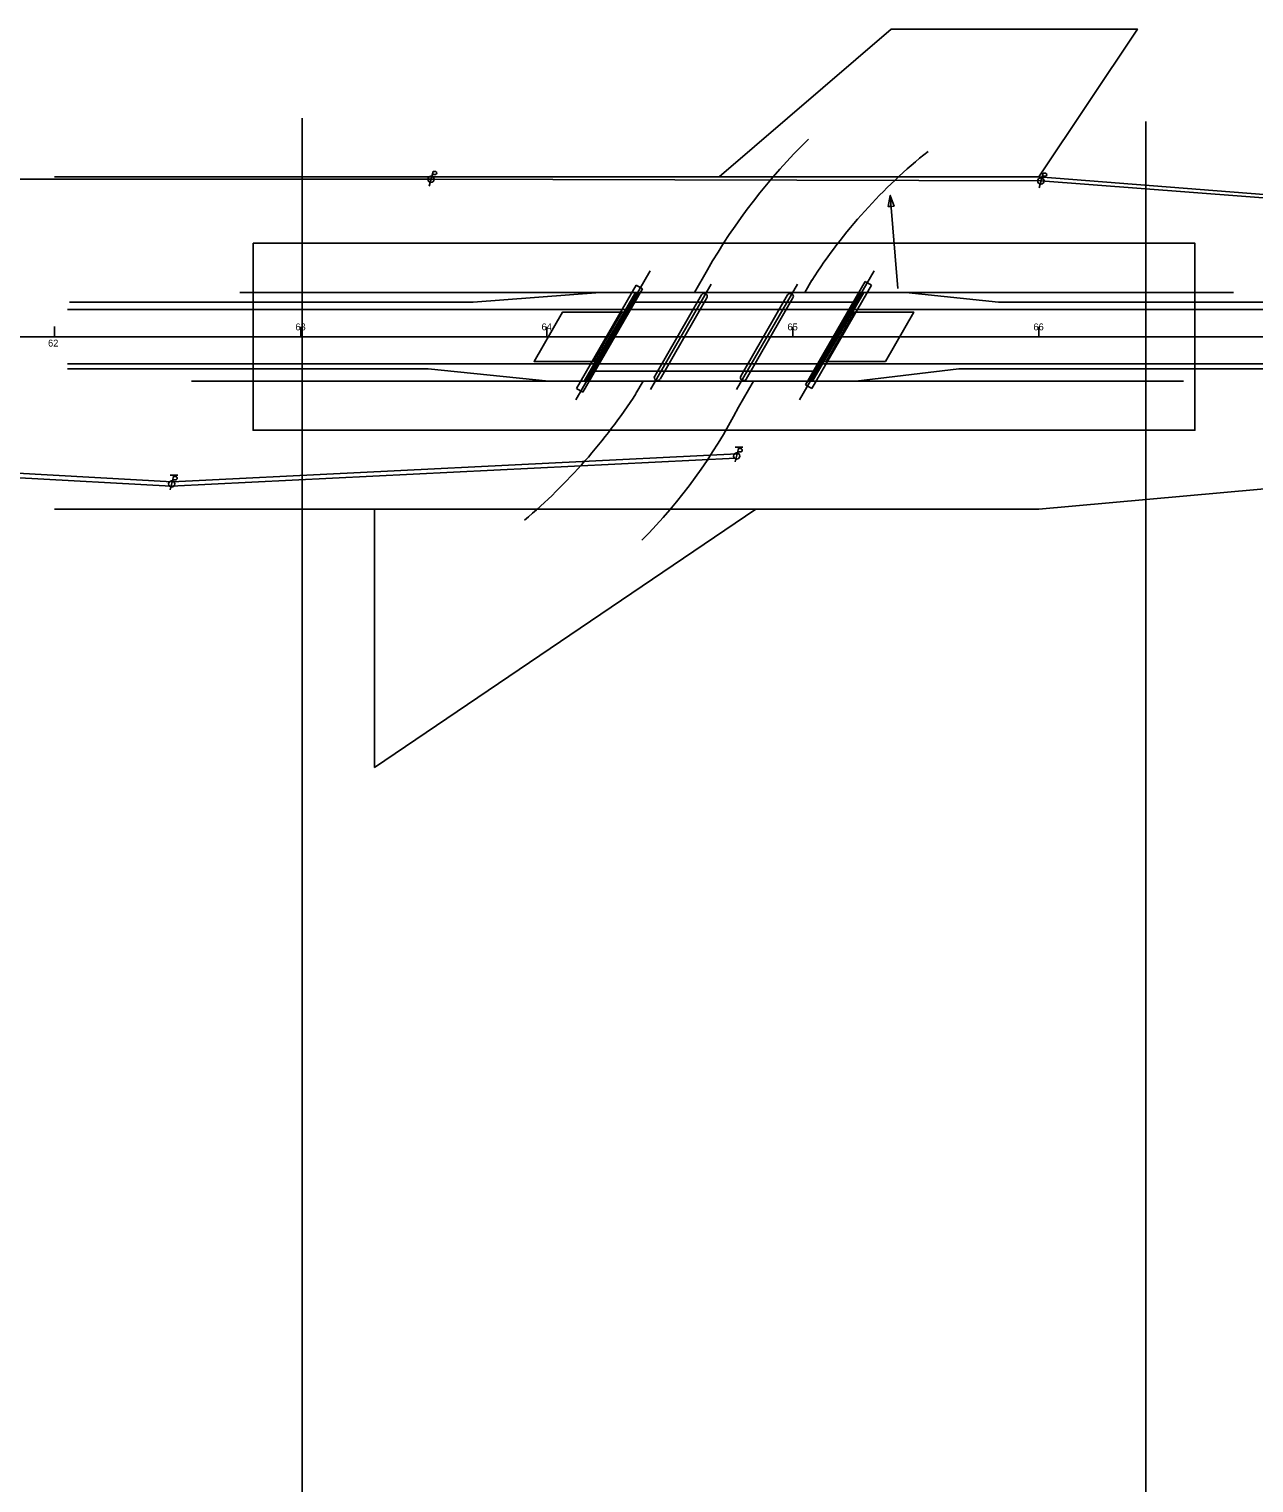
# Model space of a CAD drawing. Extents: x -2222 to 2066, y -217 to 964.
# Drawn here: x -1930 to -1432, y 374 to 964 of the extents above; entities that cross this region are included whole.
import ezdxf

# ---------------------------------------------------------------- set-up
doc = ezdxf.new("R2010")
doc.units = 0
for name, color, linetype in [('BR_X_Brg_Centerline', 7, 'Continuous'), ('BR_X_Slab_Const_Joint', 7, 'Continuous'), ('BR_X_Slab_Object', 7, 'Continuous'), ('BR_X_Sub_Centerline', 7, 'Continuous'), ('BR_X_Sub_Object', 7, 'Continuous'), ('GE_X_CL_20', 7, 'Continuous'), ('HY_X_Water_Edge', 7, 'Continuous'), ('MD_P_CONST_LIMITS', 7, 'Continuous'), ('PM_P_CL_Pass_Proh_Rt', 7, 'Continuous'), ('PM_X_Edge_Line', 7, 'Continuous'), ('PV_P_Shoulder_Rumble_Strip', 7, 'Continuous'), ('PV_X_EOP', 7, 'Continuous'), ('RD_X_GR_Lt', 7, 'Continuous'), ('RD_X_GR_Rt', 7, 'Continuous'), ('RW_X_Esmt_CH', 7, 'Continuous'), ('RW_X_Fee_RW', 7, 'Continuous'), ('SC_Scratch1', 7, 'Continuous'), ('SC_Scratch3', 7, 'Continuous'), ('UT_X_Electric_Cells', 7, 'Continuous'), ('UT_X_Gas', 7, 'Continuous'), ('UT_X_Overhead_Electric', 7, 'Continuous'), ('UT_X_Overhead_Telecom', 7, 'Continuous')]:
    doc.layers.add(name, color=color, linetype=linetype)

msp = doc.modelspace()

# ---------------------------------------------------------------- linework, layer by layer
at = {"layer": 'BR_X_Brg_Centerline'}
for p, q in [((-1677.87, 866.17), (-1708.11, 813.79)), ((-1586.87, 866.17), (-1617.11, 813.79))]:
    msp.add_line(p, q, dxfattribs=at)
at = {"layer": 'BR_X_Slab_Const_Joint'}
for p, q in [((-1686.13, 853.37), (-1593.54, 853.37)), ((-1702.29, 825.37), (-1609.7, 825.37))]:
    msp.add_line(p, q, dxfattribs=at)
at = {"layer": 'BR_X_Slab_Object'}
msp.add_lwpolyline([(-1683.82, 857.37), (-1704.6, 821.37), (-1611.86, 821.37), (-1591.08, 857.37)], close=True, dxfattribs=at)
at = {"layer": 'BR_X_Sub_Centerline'}
for p, q in [((-1677.71, 817.95), (-1653.01, 860.73)), ((-1618, 860.74), (-1642.74, 817.89))]:
    msp.add_line(p, q, dxfattribs=at)
at = {"layer": 'BR_X_Sub_Object'}
for p, q in [((-1683.53, 860.37), (-1707.78, 818.37)), ((-1705.18, 816.87), (-1680.97, 858.8)), ((-1683.09, 857.37), (-1703.88, 821.37)), ((-1703.16, 821.37), (-1682.37, 857.37)), ((-1680.97, 858.8), (-1683.57, 860.3)), ((-1590.5, 861.87), (-1614.74, 819.88)), ((-1613.3, 821.37), (-1592.52, 857.37)), ((-1591.8, 857.37), (-1612.58, 821.37)), ((-1612.15, 818.37), (-1587.9, 860.37)), ((-1587.9, 860.37), (-1590.5, 861.87)), ((-1656.97, 856.37), (-1676.01, 823.4)), ((-1673.84, 822.15), (-1654.81, 855.12)), ((-1621.97, 856.38), (-1641, 823.41)), ((-1638.84, 822.16), (-1619.8, 855.13)), ((-1700.85, 829.37), (-1689.3, 849.37)), ((-1606.38, 829.37), (-1594.83, 849.37)), ((-1707.78, 818.37), (-1705.18, 816.87)), ((-1614.74, 819.88), (-1612.15, 818.38))]:
    msp.add_line(p, q, dxfattribs=at)
for points in [[(-1688.44, 849.37), (-1713.44, 849.37), (-1724.98, 829.37), (-1699.98, 829.37)], [(-1607.24, 829.37), (-1582.24, 829.37), (-1570.7, 849.37), (-1595.7, 849.37)]]:
    msp.add_lwpolyline(points, dxfattribs=at)
for centre, start, end in [((-1655.89, 855.74), 330, 150), ((-1620.88, 855.75), 330, 150), ((-1674.92, 822.77), 150, 324.13716), ((-1639.92, 822.78), 150, 330)]:
    msp.add_arc(centre, 1.25, start, end, dxfattribs=at)
at = {"layer": 'GE_X_CL_20'}
for p, q in [((-1914.68, 839.37), (-1418.65, 839.37)), ((-1819.84, 839.37), (-1819.84, 841.37)), ((-1719.84, 839.37), (-1719.84, 841.37)), ((-1619.84, 839.37), (-1619.84, 841.37)), ((-1519.84, 839.37), (-1519.84, 841.37))]:
    msp.add_line(p, q, dxfattribs=at)
at = {"layer": 'HY_X_Water_Edge'}
for p, q in [((-1659.86, 857.37), (-1654.57, 866.53)), ((-1615.04, 857.37), (-1612.2, 862.29)), ((-1680.64, 821.37), (-1683.61, 816.24)), ((-1635.83, 821.37), (-1641.99, 810.69))]:
    msp.add_line(p, q, dxfattribs=at)
for centre, radius, start, end in [((-1444.17, 746.19), 242.38, 134.30725, 150.23356), ((-1427.35, 742.97), 220.01, 128.70044, 147.15858), ((-1882.04, 945.3), 236.71, 310.32329, 326.95848), ((-1836.67, 910.83), 218.92, 315.25171, 332.77778)]:
    msp.add_arc(centre, radius, start, end, dxfattribs=at)
at = {"layer": 'MD_P_CONST_LIMITS'}
msp.add_lwpolyline([(-1839.21, 877.37), (-1456.47, 877.37), (-1456.47, 801.37), (-1839.21, 801.37)], close=True, dxfattribs=at)
at = {"layer": 'PM_P_CL_Pass_Proh_Rt'}
msp.add_line((-1914.68, 839.37), (-1418.65, 839.37), dxfattribs=at)
at = {"layer": 'PM_X_Edge_Line'}
for p, q in [((-1914.68, 850.37), (-1418.44, 850.37)), ((-1914.68, 828.37), (-1418.44, 828.37))]:
    msp.add_line(p, q, dxfattribs=at)
at = {"layer": 'PV_P_Shoulder_Rumble_Strip'}
for p, q in [((-1694.21, 839.37), (-1744.21, 839.37)), ((-1601.47, 839.37), (-1551.47, 839.37))]:
    msp.add_line(p, q, dxfattribs=at)
at = {"layer": 'PV_X_EOP'}
for points in [[(-1683.82, 857.37), (-1698.13, 857.37), (-1749.77, 853.37), (-1913.75, 853.37)], [(-1591.08, 857.37), (-1573.9, 857.37), (-1536.29, 853.37), (-1361.15, 853.37)], [(-1704.6, 821.37), (-1719.06, 821.37), (-1767.99, 826.37), (-1914.68, 826.37)], [(-1611.86, 821.37), (-1594.23, 821.37), (-1552.45, 826.37), (-1401.79, 826.37)]]:
    msp.add_lwpolyline(points, dxfattribs=at)
at = {"layer": 'RD_X_GR_Lt'}
msp.add_line((-1844.52, 857.37), (-1440.75, 857.37), dxfattribs=at)
at = {"layer": 'RD_X_GR_Rt'}
msp.add_line((-1864.19, 821.37), (-1461.11, 821.37), dxfattribs=at)
at = {"layer": 'RW_X_Esmt_CH'}
for points in [[(-1649.84, 904.37), (-1579.84, 964.37), (-1479.84, 964.37), (-1519.84, 904.37)], [(-1789.84, 769.37), (-1789.84, 664.37), (-1634.84, 769.37)]]:
    msp.add_lwpolyline(points, dxfattribs=at)
at = {"layer": 'RW_X_Fee_RW'}
for points in [[(-1919.84, 904.37), (-1519.84, 904.37), (-1074.8, 869.37)], [(-1919.84, 769.37), (-1519.84, 769.37), (-1074.8, 809.37)]]:
    msp.add_lwpolyline(points, dxfattribs=at)
at = {"layer": 'SC_Scratch1'}
for p, q in [((-1766.75, 903.95), (-1766.58, 904.6)), ((-1518.9, 903.26), (-1518.72, 903.91)), ((-1767.25, 902.09), (-1767.07, 902.74)), ((-1519.4, 901.4), (-1519.22, 902.05)), ((-1914.68, 839.37), (-2219.84, 839.37)), ((-1919.84, 839.37), (-1919.84, 843.57)), ((-1819.84, 841.37), (-1819.84, 843.37)), ((-1719.84, 841.37), (-1719.84, 843.37)), ((-1619.84, 841.37), (-1619.84, 843.37)), ((-1519.84, 841.37), (-1519.84, 843.37)), ((-1642.55, 791.5), (-1642.37, 792.15)), ((-1643.05, 789.64), (-1642.87, 790.29)), ((-1872.14, 780.15), (-1871.97, 780.81)), ((-1872.64, 778.29), (-1872.47, 778.95))]:
    msp.add_line(p, q, dxfattribs=at)
msp.add_lwpolyline([(-1580.28, 896.82), (-1581.12, 892.23), (-1579.91, 892.33), (-1578.7, 892.43), (-1580.27, 896.79), (-1577.2, 858.99)], dxfattribs=at)
at = {"layer": 'SC_Scratch3'}
for p, q in [((-1819.21, 18.08), (-1819.21, 928.19)), ((-1476.47, 16.67), (-1476.47, 926.77))]:
    msp.add_line(p, q, dxfattribs=at)
at = {"layer": 'UT_X_Electric_Cells'}
for p, q in [((-1766.06, 906.54), (-1767.66, 900.54)), ((-1766.4, 905.27), (-1765.21, 905.27)), ((-1766.06, 906.54), (-1765.21, 906.54)), ((-1518.2, 905.85), (-1519.81, 899.85)), ((-1518.55, 904.58), (-1517.35, 904.58)), ((-1518.2, 905.85), (-1517.35, 905.85))]:
    msp.add_line(p, q, dxfattribs=at)
for centre in [(-1766.91, 903.34), (-1519.06, 902.65)]:
    msp.add_circle(centre, 1.3, dxfattribs=at)
for centre in [(-1765.19, 905.91), (-1517.34, 905.21)]:
    msp.add_arc(centre, 0.638, 268.8767, 91.1233, dxfattribs=at)
at = {"layer": 'UT_X_Gas'}
for p, q in [((-1640.15, 794.5), (-1643.35, 794.5)), ((-1641.75, 794.5), (-1643.35, 788.5)), ((-1642.25, 792.62), (-1641.06, 792.62)), ((-1641.91, 793.9), (-1641.06, 793.9)), ((-1871.34, 783.15), (-1872.95, 777.15)), ((-1869.74, 783.15), (-1872.94, 783.15)), ((-1871.84, 781.28), (-1870.65, 781.28)), ((-1871.5, 782.55), (-1870.65, 782.55))]:
    msp.add_line(p, q, dxfattribs=at)
for centre in [(-1642.71, 790.9), (-1872.3, 779.55)]:
    msp.add_circle(centre, 1.3, dxfattribs=at)
for centre in [(-1641.04, 793.26), (-1870.64, 781.91)]:
    msp.add_arc(centre, 0.638, 268.8767, 91.1233, dxfattribs=at)
at = {"layer": 'UT_X_Overhead_Electric'}
for points in [[(-1969.05, 903.34), (-1766.91, 903.34), (-1519.06, 902.65), (-1315.19, 887.1)], [(-2000.31, 787.59), (-1872.06, 780.48), (-1642.46, 791.83)]]:
    msp.add_lwpolyline(points, dxfattribs=at)
at = {"layer": 'UT_X_Overhead_Telecom'}
msp.add_lwpolyline([(-2000.81, 785.73), (-1872.55, 778.62), (-1642.96, 789.97)], dxfattribs=at)

# ---------------------------------------------------------------- texts
at = {"layer": 'GE_X_CL_20'}
for s, p in [('63', (-1821.99, 841.97)), ('64', (-1721.99, 841.97)), ('65', (-1622.03, 841.97)), ('66', (-1522.08, 841.97))]:
    msp.add_text(s, height=2.8, dxfattribs=at).set_placement(p)
at = {"layer": 'SC_Scratch1'}
msp.add_text('62', height=2.8, dxfattribs=at).set_placement((-1922.52, 835.38))

doc.saveas('drawing.dxf')
